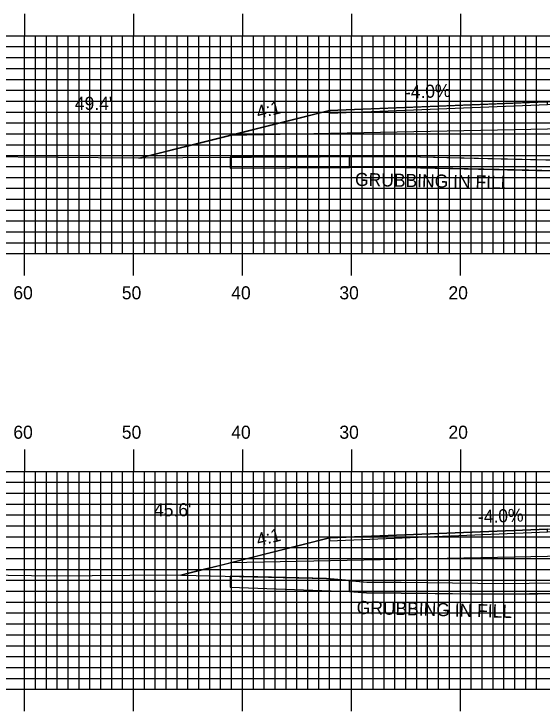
# Model space of a CAD drawing. Extents: x 1773596 to 1773940, y 442591 to 442811.
# Drawn here: x 1773701.2 to 1773749.6, y 442696.7 to 442760.7 of the extents above; entities that cross this region are included whole.
import ezdxf

# ---------------------------------------------------------------- set-up
doc = ezdxf.new("R2010")
doc.units = 0
for name, color, linetype in [('ANNOTATION', 7, 'Continuous'), ('D_Roadway_Centerline', 7, 'Continuous'), ('D_Roadway_Edge_Shoulder', 7, 'Continuous'), ('D_Roadway_SlopeLines', 7, 'Continuous'), ('D_Roadway_SubGrade', 7, 'Continuous'), ('D_Text_Standard', 7, 'Continuous'), ('GRUBBING IN FILL', 7, 'Continuous'), ('H_V ANNOTATION', 7, 'Continuous'), ('MAJOR', 7, 'Continuous'), ('MINOR', 7, 'Continuous'), ('S_Roadway_Centerline', 7, 'Continuous')]:
    doc.layers.add(name, color=color, linetype=linetype)

msp = doc.modelspace()

# ---------------------------------------------------------------- linework, layer by layer
at = {"layer": 'D_Roadway_Centerline'}
for points in [[(1773712.795, 442747.466), (1773721.014, 442749.521), (1773730.146, 442751.804), (1773730.147, 442751.804), (1773749.27, 442752.569), (1773750.146, 442752.604), (1773753.801, 442752.677), (1773762.146, 442752.844), (1773765.553, 442752.776), (1773774.146, 442752.604), (1773777.853, 442752.456), (1773782.146, 442752.284), (1773792.32, 442749.74), (1773798.209, 442748.268), (1773803.986, 442746.824)], [(1773716.496, 442709.142), (1773721.014, 442710.271), (1773730.146, 442712.554), (1773730.147, 442712.555), (1773750.146, 442713.354), (1773759.4, 442713.539), (1773762.146, 442713.594), (1773774.146, 442713.354), (1773782.146, 442713.034), (1773792.32, 442710.49), (1773804.447, 442707.459), (1773804.593, 442707.422)]]:
    msp.add_lwpolyline(points, dxfattribs=at)
at = {"layer": 'D_Roadway_Edge_Shoulder'}
for points in [[(1773750.146, 442752.604), (1773730.146, 442751.804), (1773730.146, 442751.554), (1773750.146, 442752.354)], [(1773750.146, 442713.354), (1773730.146, 442712.554), (1773730.146, 442712.304), (1773750.146, 442713.104)]]:
    msp.add_lwpolyline(points, close=True, dxfattribs=at)
at = {"layer": 'D_Roadway_SlopeLines'}
for points in [[(1773730.146, 442751.804), (1773719.972, 442749.26), (1773718.146, 442748.804), (1773712.795, 442747.466)], [(1773730.146, 442712.554), (1773719.972, 442710.01), (1773718.146, 442709.554), (1773716.496, 442709.142)]]:
    msp.add_lwpolyline(points, dxfattribs=at)
at = {"layer": 'D_Roadway_SubGrade'}
for points in [[(1773750.146, 442750.104), (1773721.014, 442749.521), (1773730.146, 442751.804), (1773730.146, 442751.554), (1773750.146, 442752.354), (1773762.146, 442752.594), (1773774.146, 442752.354), (1773782.146, 442752.034), (1773782.146, 442752.284), (1773792.32, 442749.74), (1773774.146, 442750.104), (1773762.146, 442750.344)], [(1773750.146, 442710.854), (1773721.014, 442710.271), (1773730.146, 442712.554), (1773730.146, 442712.304), (1773750.146, 442713.104), (1773762.146, 442713.344), (1773774.145, 442713.104), (1773782.146, 442712.784), (1773782.146, 442713.034), (1773792.32, 442710.49), (1773774.145, 442710.854), (1773762.146, 442711.094)]]:
    msp.add_lwpolyline(points, close=True, dxfattribs=at)
at = {"layer": 'GRUBBING IN FILL'}
for p, q in [((1773731.972, 442747.569), (1773721.014, 442747.51)), ((1773731.972, 442747.569), (1773731.972, 442746.569)), ((1773731.972, 442746.569), (1773731.972, 442747.569)), ((1773729.858, 442708.83), (1773721.014, 442709.037)), ((1773729.858, 442708.83), (1773721.014, 442709.037)), ((1773721.014, 442709.037), (1773721.014, 442708.037)), ((1773731.972, 442708.646), (1773729.858, 442708.83)), ((1773731.972, 442708.646), (1773729.858, 442708.83)), ((1773731.972, 442708.646), (1773731.972, 442707.643)), ((1773731.972, 442708.646), (1773731.972, 442708.646)), ((1773731.972, 442707.643), (1773731.972, 442708.646)), ((1773721.014, 442708.037), (1773731.972, 442707.643)), ((1773731.972, 442707.643), (1773731.972, 442707.643))]:
    msp.add_line(p, q, dxfattribs=at)
for points in [[(1773721.014, 442747.51), (1773721.014, 442746.51), (1773731.972, 442746.569)], [(1773721.014, 442747.51), (1773721.014, 442746.51), (1773731.972, 442746.569)], [(1773731.972, 442747.569), (1773737.184, 442747.572), (1773747.155, 442747.348), (1773757.127, 442747.124), (1773762.146, 442747.102), (1773762.146, 442746.102), (1773757.113, 442746.124), (1773747.136, 442746.348), (1773737.159, 442746.573), (1773731.972, 442746.569)], [(1773731.972, 442746.569), (1773735.577, 442746.589), (1773736.302, 442746.597), (1773737.159, 442746.573), (1773757.113, 442746.124), (1773762.077, 442746.102), (1773771.312, 442746.189), (1773779.689, 442746.126), (1773787.164, 442746.123), (1773792.32, 442746.12)], [(1773731.972, 442746.569), (1773735.577, 442746.589), (1773736.302, 442746.597), (1773737.159, 442746.573), (1773757.113, 442746.124), (1773762.077, 442746.102), (1773771.312, 442746.189), (1773779.689, 442746.126), (1773787.164, 442746.123), (1773792.32, 442746.12)], [(1773721.014, 442709.037), (1773721.014, 442708.037), (1773731.972, 442707.643)], [(1773721.014, 442709.037), (1773721.014, 442708.037), (1773731.972, 442707.643)], [(1773721.014, 442709.037), (1773721.014, 442708.037), (1773731.972, 442707.643)], [(1773731.972, 442708.646), (1773733.575, 442708.507), (1773735.151, 442708.496), (1773736.726, 442708.485), (1773741.423, 442708.436), (1773746.12, 442708.386), (1773750.848, 442708.442), (1773755.576, 442708.498), (1773758.141, 442708.46), (1773762.146, 442708.3), (1773762.146, 442707.299), (1773758.114, 442707.46), (1773755.575, 442707.498), (1773750.848, 442707.442), (1773746.12, 442707.386), (1773741.419, 442707.436), (1773736.718, 442707.485), (1773733.528, 442707.507), (1773731.972, 442707.643)], [(1773731.972, 442707.643), (1773733.528, 442707.507), (1773736.718, 442707.485), (1773746.12, 442707.386), (1773755.575, 442707.498), (1773758.114, 442707.46), (1773768.184, 442707.059), (1773779.76, 442706.845), (1773780.528, 442706.842), (1773792.32, 442707.012)], [(1773731.972, 442707.643), (1773733.528, 442707.507), (1773736.718, 442707.485), (1773746.12, 442707.386), (1773755.575, 442707.498), (1773758.114, 442707.46), (1773768.184, 442707.059), (1773779.76, 442706.845), (1773780.528, 442706.842), (1773792.32, 442707.012)]]:
    msp.add_lwpolyline(points, dxfattribs=at)
for points in [[(1773731.972, 442747.569), (1773737.184, 442747.572), (1773747.155, 442747.348), (1773757.127, 442747.124), (1773762.146, 442747.102), (1773762.146, 442746.102), (1773757.113, 442746.124), (1773747.136, 442746.348), (1773737.159, 442746.573), (1773731.972, 442746.569)], [(1773731.972, 442708.646), (1773733.575, 442708.507), (1773735.151, 442708.496), (1773736.726, 442708.485), (1773741.423, 442708.436), (1773746.12, 442708.386), (1773750.848, 442708.442), (1773755.576, 442708.498), (1773758.141, 442708.46), (1773762.146, 442708.3), (1773762.146, 442707.299), (1773758.114, 442707.46), (1773755.575, 442707.498), (1773750.848, 442707.442), (1773746.12, 442707.386), (1773741.419, 442707.436), (1773736.718, 442707.485), (1773733.528, 442707.507), (1773731.972, 442707.643)]]:
    msp.add_lwpolyline(points, close=True, dxfattribs=at)
at = {"layer": 'MAJOR'}
for p, q in [((1773702.146, 442760.669), (1773702.146, 442758.665)), ((1773712.146, 442760.669), (1773712.146, 442758.665)), ((1773722.146, 442760.669), (1773722.146, 442758.665)), ((1773732.146, 442760.669), (1773732.146, 442758.665)), ((1773742.146, 442760.669), (1773742.146, 442758.665)), ((1773622.146, 442758.665), (1773902.146, 442758.665)), ((1773622.146, 442758.665), (1773902.146, 442758.665)), ((1773702.146, 442738.665), (1773702.146, 442758.665)), ((1773712.146, 442738.665), (1773712.146, 442758.665)), ((1773722.146, 442738.665), (1773722.146, 442758.665)), ((1773732.146, 442738.665), (1773732.146, 442758.665)), ((1773742.146, 442738.665), (1773742.146, 442758.665)), ((1773622.146, 442753.665), (1773902.146, 442753.665)), ((1773622.146, 442748.665), (1773902.146, 442748.665)), ((1773622.146, 442743.665), (1773902.146, 442743.665)), ((1773622.146, 442738.665), (1773902.146, 442738.665)), ((1773622.146, 442738.665), (1773902.146, 442738.665)), ((1773702.146, 442736.661), (1773702.146, 442738.665)), ((1773712.146, 442736.661), (1773712.146, 442738.665)), ((1773722.146, 442736.661), (1773722.146, 442738.665)), ((1773732.146, 442736.661), (1773732.146, 442738.665)), ((1773742.146, 442736.661), (1773742.146, 442738.665)), ((1773702.146, 442720.669), (1773702.146, 442718.665)), ((1773712.146, 442720.669), (1773712.146, 442718.665)), ((1773722.146, 442720.669), (1773722.146, 442718.665)), ((1773732.146, 442720.669), (1773732.146, 442718.665)), ((1773742.146, 442720.669), (1773742.146, 442718.665)), ((1773622.146, 442718.665), (1773902.146, 442718.665)), ((1773622.146, 442718.665), (1773902.146, 442718.665)), ((1773702.146, 442698.665), (1773702.146, 442718.665)), ((1773712.146, 442698.665), (1773712.146, 442718.665)), ((1773722.146, 442698.665), (1773722.146, 442718.665)), ((1773732.146, 442698.665), (1773732.146, 442718.665)), ((1773742.146, 442698.665), (1773742.146, 442718.665)), ((1773622.146, 442713.665), (1773902.146, 442713.665)), ((1773622.146, 442708.665), (1773902.146, 442708.665)), ((1773622.146, 442703.665), (1773902.146, 442703.665)), ((1773622.146, 442698.665), (1773902.146, 442698.665)), ((1773622.146, 442698.665), (1773902.146, 442698.665)), ((1773702.146, 442696.661), (1773702.146, 442698.665)), ((1773712.146, 442696.661), (1773712.146, 442698.665)), ((1773722.146, 442696.661), (1773722.146, 442698.665)), ((1773732.146, 442696.661), (1773732.146, 442698.665)), ((1773742.146, 442696.661), (1773742.146, 442698.665))]:
    msp.add_line(p, q, dxfattribs=at)
at = {"layer": 'MINOR'}
for p, q in [((1773703.146, 442738.665), (1773703.146, 442758.665)), ((1773704.146, 442738.665), (1773704.146, 442758.665)), ((1773705.146, 442738.665), (1773705.146, 442758.665)), ((1773706.146, 442738.665), (1773706.146, 442758.665)), ((1773707.146, 442738.665), (1773707.146, 442758.665)), ((1773708.146, 442738.665), (1773708.146, 442758.665)), ((1773709.146, 442738.665), (1773709.146, 442758.665)), ((1773710.146, 442738.665), (1773710.146, 442758.665)), ((1773711.146, 442738.665), (1773711.146, 442758.665)), ((1773713.146, 442738.665), (1773713.146, 442758.665)), ((1773714.146, 442738.665), (1773714.146, 442758.665)), ((1773715.146, 442738.665), (1773715.146, 442758.665)), ((1773716.146, 442738.665), (1773716.146, 442758.665)), ((1773717.146, 442738.665), (1773717.146, 442758.665)), ((1773718.146, 442738.665), (1773718.146, 442758.665)), ((1773719.146, 442738.665), (1773719.146, 442758.665)), ((1773720.146, 442738.665), (1773720.146, 442758.665)), ((1773721.146, 442738.665), (1773721.146, 442758.665)), ((1773723.146, 442738.665), (1773723.146, 442758.665)), ((1773724.146, 442738.665), (1773724.146, 442758.665)), ((1773725.146, 442738.665), (1773725.146, 442758.665)), ((1773726.146, 442738.665), (1773726.146, 442758.665)), ((1773727.146, 442738.665), (1773727.146, 442758.665)), ((1773728.146, 442738.665), (1773728.146, 442758.665)), ((1773729.146, 442738.665), (1773729.146, 442758.665)), ((1773730.146, 442738.665), (1773730.146, 442758.665)), ((1773731.146, 442738.665), (1773731.146, 442758.665)), ((1773733.146, 442738.665), (1773733.146, 442758.665)), ((1773734.146, 442738.665), (1773734.146, 442758.665)), ((1773735.146, 442738.665), (1773735.146, 442758.665)), ((1773736.146, 442738.665), (1773736.146, 442758.665)), ((1773737.146, 442738.665), (1773737.146, 442758.665)), ((1773738.146, 442738.665), (1773738.146, 442758.665)), ((1773739.146, 442738.665), (1773739.146, 442758.665)), ((1773740.146, 442738.665), (1773740.146, 442758.665)), ((1773741.146, 442738.665), (1773741.146, 442758.665)), ((1773743.146, 442738.665), (1773743.146, 442758.665)), ((1773744.146, 442738.665), (1773744.146, 442758.665)), ((1773745.146, 442738.665), (1773745.146, 442758.665)), ((1773746.146, 442738.665), (1773746.146, 442758.665)), ((1773747.146, 442738.665), (1773747.146, 442758.665)), ((1773748.146, 442738.665), (1773748.146, 442758.665)), ((1773749.146, 442738.665), (1773749.146, 442758.665)), ((1773622.146, 442757.665), (1773902.146, 442757.665)), ((1773622.146, 442756.665), (1773902.146, 442756.665)), ((1773622.146, 442755.665), (1773902.146, 442755.665)), ((1773622.146, 442754.665), (1773902.146, 442754.665)), ((1773622.146, 442752.665), (1773902.146, 442752.665)), ((1773622.146, 442751.665), (1773902.146, 442751.665)), ((1773622.146, 442750.665), (1773902.146, 442750.665)), ((1773622.146, 442749.665), (1773902.146, 442749.665)), ((1773622.146, 442747.665), (1773902.146, 442747.665)), ((1773622.146, 442746.665), (1773902.146, 442746.665)), ((1773622.146, 442745.665), (1773902.146, 442745.665)), ((1773622.146, 442744.665), (1773902.146, 442744.665)), ((1773622.146, 442742.665), (1773902.146, 442742.665)), ((1773622.146, 442741.665), (1773902.146, 442741.665)), ((1773622.146, 442740.665), (1773902.146, 442740.665)), ((1773622.146, 442739.665), (1773902.146, 442739.665)), ((1773703.146, 442698.665), (1773703.146, 442718.665)), ((1773704.146, 442698.665), (1773704.146, 442718.665)), ((1773705.146, 442698.665), (1773705.146, 442718.665)), ((1773706.146, 442698.665), (1773706.146, 442718.665)), ((1773707.146, 442698.665), (1773707.146, 442718.665)), ((1773708.146, 442698.665), (1773708.146, 442718.665)), ((1773709.146, 442698.665), (1773709.146, 442718.665)), ((1773710.146, 442698.665), (1773710.146, 442718.665)), ((1773711.146, 442698.665), (1773711.146, 442718.665)), ((1773713.146, 442698.665), (1773713.146, 442718.665)), ((1773714.146, 442698.665), (1773714.146, 442718.665)), ((1773715.146, 442698.665), (1773715.146, 442718.665)), ((1773716.146, 442698.665), (1773716.146, 442718.665)), ((1773717.146, 442698.665), (1773717.146, 442718.665)), ((1773718.146, 442698.665), (1773718.146, 442718.665)), ((1773719.146, 442698.665), (1773719.146, 442718.665)), ((1773720.146, 442698.665), (1773720.146, 442718.665)), ((1773721.146, 442698.665), (1773721.146, 442718.665)), ((1773723.146, 442698.665), (1773723.146, 442718.665)), ((1773724.146, 442698.665), (1773724.146, 442718.665)), ((1773725.146, 442698.665), (1773725.146, 442718.665)), ((1773726.146, 442698.665), (1773726.146, 442718.665)), ((1773727.146, 442698.665), (1773727.146, 442718.665)), ((1773728.146, 442698.665), (1773728.146, 442718.665)), ((1773729.146, 442698.665), (1773729.146, 442718.665)), ((1773730.146, 442698.665), (1773730.146, 442718.665)), ((1773731.146, 442698.665), (1773731.146, 442718.665)), ((1773733.146, 442698.665), (1773733.146, 442718.665)), ((1773734.146, 442698.665), (1773734.146, 442718.665)), ((1773735.146, 442698.665), (1773735.146, 442718.665)), ((1773736.146, 442698.665), (1773736.146, 442718.665)), ((1773737.146, 442698.665), (1773737.146, 442718.665)), ((1773738.146, 442698.665), (1773738.146, 442718.665)), ((1773739.146, 442698.665), (1773739.146, 442718.665)), ((1773740.146, 442698.665), (1773740.146, 442718.665)), ((1773741.146, 442698.665), (1773741.146, 442718.665)), ((1773743.146, 442698.665), (1773743.146, 442718.665)), ((1773744.146, 442698.665), (1773744.146, 442718.665)), ((1773745.146, 442698.665), (1773745.146, 442718.665)), ((1773746.146, 442698.665), (1773746.146, 442718.665)), ((1773747.146, 442698.665), (1773747.146, 442718.665)), ((1773748.146, 442698.665), (1773748.146, 442718.665)), ((1773749.146, 442698.665), (1773749.146, 442718.665)), ((1773622.146, 442717.665), (1773902.146, 442717.665)), ((1773622.146, 442716.665), (1773902.146, 442716.665)), ((1773622.146, 442715.665), (1773902.146, 442715.665)), ((1773622.146, 442714.665), (1773902.146, 442714.665)), ((1773622.146, 442712.665), (1773902.146, 442712.665)), ((1773622.146, 442711.665), (1773902.146, 442711.665)), ((1773622.146, 442710.665), (1773902.146, 442710.665)), ((1773622.146, 442709.665), (1773902.146, 442709.665)), ((1773622.146, 442707.665), (1773902.146, 442707.665)), ((1773622.146, 442706.665), (1773902.146, 442706.665)), ((1773622.146, 442705.665), (1773902.146, 442705.665)), ((1773622.146, 442704.665), (1773902.146, 442704.665)), ((1773622.146, 442702.665), (1773902.146, 442702.665)), ((1773622.146, 442701.665), (1773902.146, 442701.665)), ((1773622.146, 442700.665), (1773902.146, 442700.665)), ((1773622.146, 442699.665), (1773902.146, 442699.665))]:
    msp.add_line(p, q, dxfattribs=at)
at = {"layer": 'S_Roadway_Centerline'}
for points in [[(1773690.451, 442747.637), (1773712.611, 442747.464), (1773712.928, 442747.467), (1773716.667, 442747.487), (1773735.569, 442747.589), (1773736.311, 442747.597), (1773737.184, 442747.572), (1773757.127, 442747.124), (1773762.075, 442747.102), (1773771.311, 442747.189), (1773779.693, 442747.126), (1773787.165, 442747.123), (1773794.899, 442747.118), (1773801.393, 442746.842), (1773810.383, 442746.778)], [(1773698.484, 442709.156), (1773704.924, 442709.084), (1773715.249, 442709.171), (1773729.858, 442708.83), (1773733.575, 442708.507), (1773736.726, 442708.485), (1773746.12, 442708.386), (1773755.576, 442708.498), (1773758.141, 442708.46), (1773768.213, 442708.058), (1773779.772, 442707.845), (1773780.523, 442707.842), (1773792.035, 442708.008), (1773802.508, 442707.473), (1773804.384, 442707.419), (1773814.803, 442707.544)]]:
    msp.add_lwpolyline(points, dxfattribs=at)

# ---------------------------------------------------------------- texts
at = {"layer": 'ANNOTATION'}
for s, rotation, p in [('-4.0%', 2.29069, (1773737.078, 442752.883)), ('4:1', 14.03893, (1773723.594, 442751.027)), ('-4.0%', 2.2905, (1773743.778, 442713.901)), ('4:1', 14.0391, (1773723.594, 442711.778))]:
    msp.add_text(s, height=1.2, rotation=rotation, dxfattribs=at).set_placement(p)
at = {"layer": 'D_Text_Standard'}
for s, p in [("49.4'", (1773706.762, 442751.859)), ("45.6'", (1773714.028, 442714.549))]:
    msp.add_text(s, height=1.2, dxfattribs=at).set_placement(p)
at = {"layer": 'GRUBBING IN FILL'}
for rotation, p in [(358.80959, (1773732.469, 442744.887)), (358.48271, (1773732.616, 442705.584))]:
    msp.add_text('GRUBBING IN FILL', height=1.2, rotation=rotation, dxfattribs=at).set_placement(p)
at = {"layer": 'H_V ANNOTATION'}
for s, p in [('60', (1773701.118, 442734.465)), ('50', (1773711.075, 442734.465)), ('40', (1773721.118, 442734.465)), ('30', (1773731.043, 442734.465)), ('20', (1773741.054, 442734.465)), ('60', (1773701.118, 442721.665)), ('50', (1773711.075, 442721.665)), ('40', (1773721.118, 442721.665)), ('30', (1773731.043, 442721.665)), ('20', (1773741.054, 442721.665))]:
    msp.add_text(s, height=1.2, dxfattribs=at).set_placement(p)

doc.saveas('drawing.dxf')
